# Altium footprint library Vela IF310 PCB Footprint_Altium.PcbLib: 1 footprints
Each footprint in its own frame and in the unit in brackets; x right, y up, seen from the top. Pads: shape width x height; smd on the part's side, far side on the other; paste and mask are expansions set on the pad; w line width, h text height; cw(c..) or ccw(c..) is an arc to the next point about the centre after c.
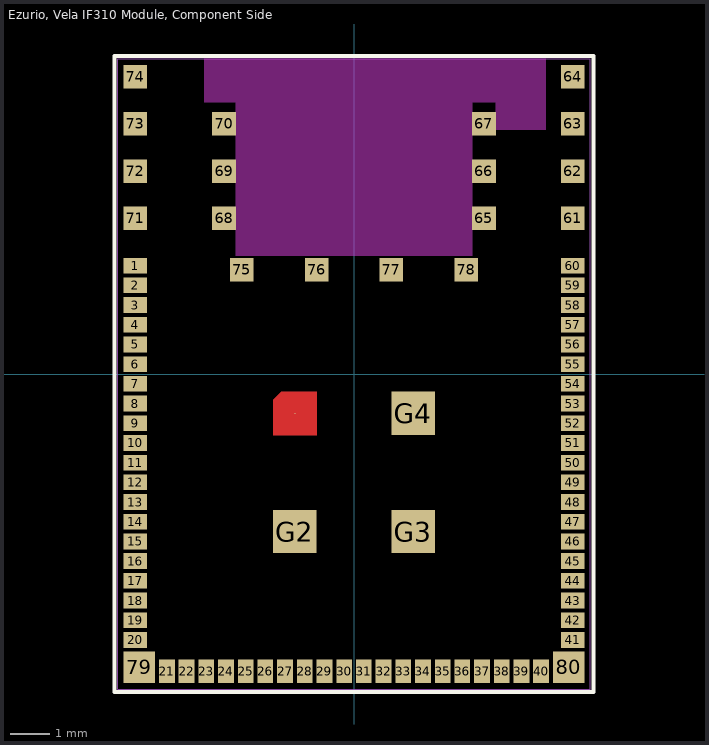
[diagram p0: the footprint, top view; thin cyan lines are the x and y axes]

## Ezurio, Vela IF310 Module, Component Side [mm] "Ezurio, Vela IF310 Module, Component Side"
height 1.9
pads (84):
  rect 0.6x0.4 smd paste-0.05 mask-0.05: 1(-5.55,2.75) 2(-5.55,2.25) 3(-5.55,1.75) 4(-5.55,1.25) 5(-5.55,0.75) 6(-5.55,0.25) 7(-5.55,-0.25) 8(-5.55,-0.75) 9(-5.55,-1.25) 10(-5.55,-1.75) 11(-5.55,-2.25) 12(-5.55,-2.75) 13(-5.55,-3.25) 14(-5.55,-3.75) 15(-5.55,-4.25) 16(-5.55,-4.75) 17(-5.55,-5.25) 18(-5.55,-5.75) 19(-5.55,-6.25) 20(-5.55,-6.75) 41(5.55,-6.75) 42(5.55,-6.25) 43(5.55,-5.75) 44(5.55,-5.25) 45(5.55,-4.75) 46(5.55,-4.25) 47(5.55,-3.75) 48(5.55,-3.25) 49(5.55,-2.75) 50(5.55,-2.25) 51(5.55,-1.75) 52(5.55,-1.25) 53(5.55,-0.75) 54(5.55,-0.25) 55(5.55,0.25) 56(5.55,0.75) 57(5.55,1.25) 58(5.55,1.75) 59(5.55,2.25) 60(5.55,2.75)
  rect 0.4x0.6 smd paste-0.05 mask-0.05: 21(-4.75,-7.55) 22(-4.25,-7.55) 23(-3.75,-7.55) 24(-3.25,-7.55) 25(-2.75,-7.55) 26(-2.25,-7.55) 27(-1.75,-7.55) 28(-1.25,-7.55) 29(-0.75,-7.55) 30(-0.25,-7.55) 31(0.25,-7.55) 32(0.75,-7.55) 33(1.25,-7.55) 34(1.75,-7.55) 35(2.25,-7.55) 36(2.75,-7.55) 37(3.25,-7.55) 38(3.75,-7.55) 39(4.25,-7.55) 40(4.75,-7.55)
  rrect0% 0.6x0.6 smd paste-0.05 mask-0.05: 61(5.55,3.95) 62(5.55,5.15) 63(5.55,6.35) 64(5.55,7.55) 65(3.3,3.95) 66(3.3,5.15) 67(3.3,6.35) 68(-3.3,3.95) 69(-3.3,5.15) 70(-3.3,6.35) 71(-5.55,3.95) 72(-5.55,5.15) 73(-5.55,6.35) 74(-5.55,7.55)
  rect 0.6x0.6 smd paste-0.05 mask-0.05: 75(-2.85,2.65) 76(-0.95,2.65) 77(0.95,2.65) 78(2.85,2.65)
  rect 0.8x0.8 smd paste-0.05 mask-0.05: 79(-5.45,-7.45) 80(5.45,-7.45)
  round 0.025 smd paste-0.05 mask-0.05: G1(-1.5,-1)
  rect 1.1x1.1 smd paste-0.05 mask-0.05: G2(-1.5,-4) G3(1.5,-4) G4(1.5,-1)
Top Layer:
  region: -1.845,-0.45 -2.05,-0.655 -2.05,-1.55 -0.95,-1.55 -0.95,-0.45
Top Overlay:
  lines w0.102: -6.078,-8.077 -6.078,8.077 6.078,8.077 6.078,-8.077 -6.078,-8.077
Keep-Out Layer:
  region: -3.8,8 -3.8,6.9 -3,6.9 -3,3 3,3 3,6.9 3.6,6.9 3.6,6.206 4.869,6.206 4.869,8 -3.8,8
Top Assembly:
  lines w0.025: -6,-8 -6,8 6,8 6,-8 -6,-8
  text ".Designator" at -8.088,9.282 h1
3D body: height 0.01, standoff 0, extent 5.3,2.6 5.8,2.9
3D body: height 0.01, standoff 0, extent 5.3,2.1 5.8,2.4
3D body: height 0.01, standoff 0, extent 5.3,1.6 5.8,1.9
3D body: height 0.01, standoff 0, extent 5.3,1.1 5.8,1.4
3D body: height 0.01, standoff 0, extent 5.3,0.6 5.8,0.9
3D body: height 0.01, standoff 0, extent 5.3,0.1 5.8,0.4
3D body: height 0.01, standoff 0, extent 5.3,-0.4 5.8,-0.1
3D body: height 0.01, standoff 0, extent 5.3,-0.9 5.8,-0.6
3D body: height 0.01, standoff 0, extent 5.3,-1.4 5.8,-1.1
3D body: height 0.01, standoff 0, extent 5.3,-1.9 5.8,-1.6
3D body: height 0.01, standoff 0, extent 5.3,-2.4 5.8,-2.1
3D body: height 0.01, standoff 0, extent 5.3,-2.9 5.8,-2.6
3D body: height 0.01, standoff 0, extent 5.3,-3.4 5.8,-3.1
3D body: height 0.01, standoff 0, extent 5.3,-3.9 5.8,-3.6
3D body: height 0.01, standoff 0, extent 5.3,-4.4 5.8,-4.1
3D body: height 0.01, standoff 0, extent 5.3,-4.9 5.8,-4.6
3D body: height 0.01, standoff 0, extent 5.3,-5.4 5.8,-5.1
3D body: height 0.01, standoff 0, extent 5.3,-5.9 5.8,-5.6
3D body: height 0.01, standoff 0, extent 5.3,-6.4 5.8,-6.1
3D body: height 0.01, standoff 0, extent 5.3,-6.9 5.8,-6.6
3D body: height 0.01, standoff 0, extent 4.6,-7.8 4.9,-7.3
3D body: height 0.01, standoff 0, extent 4.1,-7.8 4.4,-7.3
3D body: height 0.01, standoff 0, extent 3.6,-7.8 3.9,-7.3
3D body: height 0.01, standoff 0, extent 3.1,-7.8 3.4,-7.3
3D body: height 0.01, standoff 0, extent 2.6,-7.8 2.9,-7.3
3D body: height 0.01, standoff 0, extent 2.1,-7.8 2.4,-7.3
3D body: height 0.01, standoff 0, extent 1.6,-7.8 1.9,-7.3
3D body: height 0.01, standoff 0, extent 1.1,-7.8 1.4,-7.3
3D body: height 0.01, standoff 0, extent 0.6,-7.8 0.9,-7.3
3D body: height 0.01, standoff 0, extent 0.1,-7.8 0.4,-7.3
3D body: height 0.01, standoff 0, extent -0.4,-7.8 -0.1,-7.3
3D body: height 0.01, standoff 0, extent -0.9,-7.8 -0.6,-7.3
3D body: height 0.01, standoff 0, extent -1.4,-7.8 -1.1,-7.3
3D body: height 0.01, standoff 0, extent -1.9,-7.8 -1.6,-7.3
3D body: height 0.01, standoff 0, extent -2.4,-7.8 -2.1,-7.3
3D body: height 0.01, standoff 0, extent -2.9,-7.8 -2.6,-7.3
3D body: height 0.01, standoff 0, extent -3.4,-7.8 -3.1,-7.3
3D body: height 0.01, standoff 0, extent -3.9,-7.8 -3.6,-7.3
3D body: height 0.01, standoff 0, extent -4.4,-7.8 -4.1,-7.3
3D body: height 0.01, standoff 0, extent -4.9,-7.8 -4.6,-7.3
3D body: height 0.01, standoff 0, extent -5.8,-6.9 -5.3,-6.6
3D body: height 0.01, standoff 0, extent -5.8,-6.4 -5.3,-6.1
3D body: height 0.01, standoff 0, extent -5.8,-5.9 -5.3,-5.6
3D body: height 0.01, standoff 0, extent -5.8,-5.4 -5.3,-5.1
3D body: height 0.01, standoff 0, extent -5.8,-4.9 -5.3,-4.6
3D body: height 0.01, standoff 0, extent -5.8,-4.4 -5.3,-4.1
3D body: height 0.01, standoff 0, extent -5.8,-3.9 -5.3,-3.6
3D body: height 0.01, standoff 0, extent -5.8,-3.4 -5.3,-3.1
3D body: height 0.01, standoff 0, extent -5.8,-2.9 -5.3,-2.6
3D body: height 0.01, standoff 0, extent -5.8,-2.4 -5.3,-2.1
3D body: height 0.01, standoff 0, extent -5.8,-1.9 -5.3,-1.6
3D body: height 0.01, standoff 0, extent -5.8,-1.4 -5.3,-1.1
3D body: height 0.01, standoff 0, extent -5.8,-0.9 -5.3,-0.6
3D body: height 0.01, standoff 0, extent -5.8,-0.4 -5.3,-0.1
3D body: height 0.01, standoff 0, extent -5.8,0.1 -5.3,0.4
3D body: height 0.01, standoff 0, extent -5.8,0.6 -5.3,0.9
3D body: height 0.01, standoff 0, extent -5.8,1.1 -5.3,1.4
3D body: height 0.01, standoff 0, extent -5.8,1.6 -5.3,1.9
3D body: height 0.01, standoff 0, extent -5.8,2.1 -5.3,2.4
3D body: height 0.01, standoff 0, extent 5.3,3.7 5.8,4.2
3D body: height 0.01, standoff 0, extent 5.3,4.9 5.8,5.4
3D body: height 0.01, standoff 0, extent 5.3,6.1 5.8,6.6
3D body: height 0.01, standoff 0, extent 5.3,7.3 5.8,7.8
3D body: height 0.01, standoff 0, extent 3.05,6.1 3.55,6.6
3D body: height 0.01, standoff 0, extent 3.05,4.9 3.55,5.4
3D body: height 0.01, standoff 0, extent 3.05,3.7 3.55,4.2
3D body: height 0.01, standoff 0, extent 2.6,2.4 3.1,2.9
3D body: height 0.01, standoff 0, extent 0.7,2.4 1.2,2.9
3D body: height 0.01, standoff 0, extent -1.2,2.4 -0.7,2.9
3D body: height 0.01, standoff 0, extent -3.1,2.4 -2.6,2.9
3D body: height 0.01, standoff 0, extent -3.55,6.1 -3.05,6.6
3D body: height 0.01, standoff 0, extent -3.55,4.9 -3.05,5.4
3D body: height 0.01, standoff 0, extent -3.55,3.7 -3.05,4.2
3D body: height 0.01, standoff 0, extent -5.8,3.7 -5.3,4.2
3D body: height 0.01, standoff 0, extent -5.8,4.9 -5.3,5.4
3D body: height 0.01, standoff 0, extent -5.8,6.1 -5.3,6.6
3D body: height 0.01, standoff 0, extent 5.1,-7.8 5.8,-7.1
3D body: height 0.01, standoff 0, extent -5.8,-7.8 -5.1,-7.1
3D body: height 0.01, standoff 0, extent -5.8,2.6 -5.3,2.9
3D body: height 0.01, standoff 0, extent -5.8,7.3 -5.3,7.8
3D body: height 0.01, standoff 0, extent 1,-4.5 2,-3.5
3D body: height 0.01, standoff 0, extent -2,-4.5 -1,-3.5
3D body: height 0.01, standoff 0, extent 1,-1.5 2,-0.5
3D body: height 0.01, standoff 0, extent -2,-1.5 -1,-0.5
